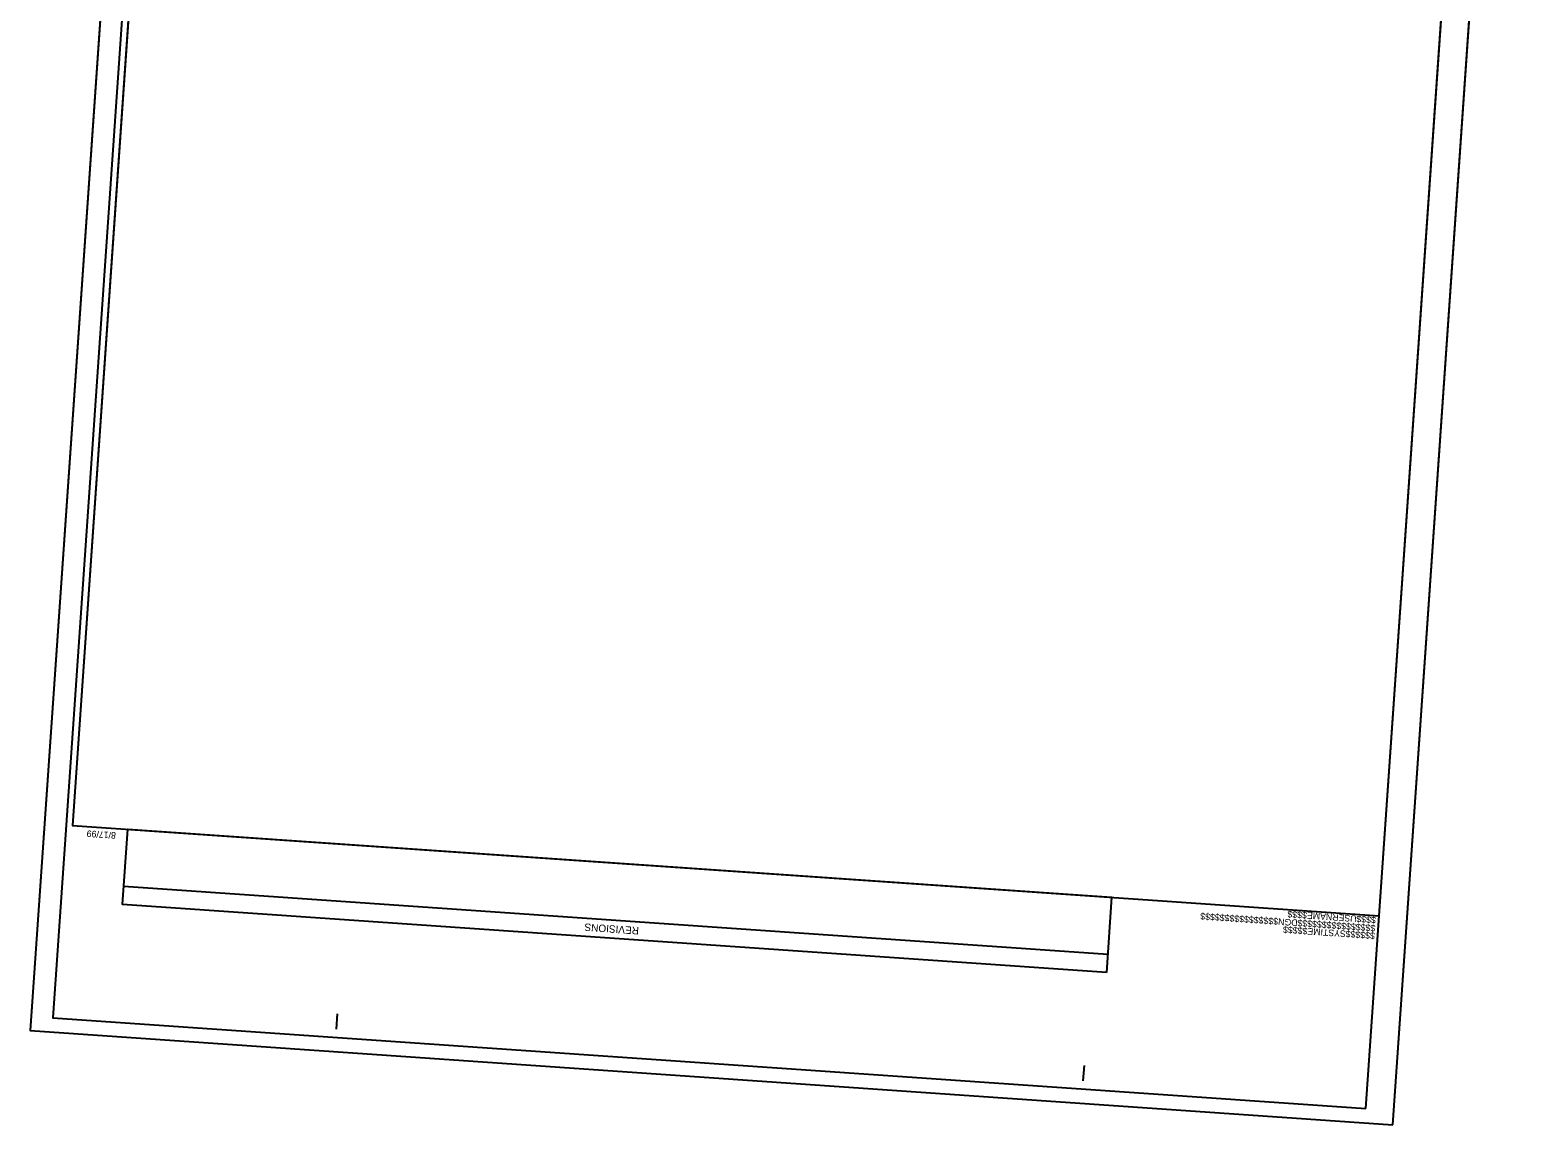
# Model space of a CAD drawing. Extents: x 2598940 to 2600149, y 728414 to 730169.
# Drawn here: x 2598940 to 2600149, y 728414 to 729291 of the extents above; entities that cross this region are included whole.
import ezdxf

# ---------------------------------------------------------------- set-up
doc = ezdxf.new("R2010")
doc.units = 0
for name, color, linetype in [('Sheet Block Revision CELL', 7, 'Continuous'), ('Sheet Clip Boundary CELL', 7, 'Continuous'), ('Sheet Cutting Line CELL', 7, 'Continuous'), ('Sheet Plan CELL', 7, 'Continuous'), ('Sheet Plot Border Inside CELL', 7, 'Continuous'), ('Sheet Plot Border Outside CELL', 7, 'Continuous')]:
    doc.layers.add(name, color=color, linetype=linetype)

msp = doc.modelspace()

# ---------------------------------------------------------------- linework, layer by layer
at = {"layer": 'Sheet Block Revision CELL'}
msp.add_line((2599804.1, 728550.2), (2599015.3, 728604.8), dxfattribs=at)
msp.add_lwpolyline([(2599803.1, 728535.7), (2599014.3, 728590.3), (2599018.5, 728650.7), (2599807.2, 728596.1)], close=True, dxfattribs=at)
at = {"layer": 'Sheet Clip Boundary CELL'}
for p, q in [((2600021.7, 728581.2), (2600125.3, 730077.7)), ((2599063.7, 729947.3), (2598974.2, 728653.7)), ((2598974.2, 728653.7), (2600021.7, 728581.2))]:
    msp.add_line(p, q, dxfattribs=at)
at = {"layer": 'Sheet Cutting Line CELL'}
for p, q in [((2599056.5, 730168.7), (2598940.3, 728489.2)), ((2600032.7, 728413.6), (2600148.9, 730093.1)), ((2598940.3, 728489.2), (2600032.7, 728413.6))]:
    msp.add_line(p, q, dxfattribs=at)
at = {"layer": 'Sheet Plan CELL'}
for p, q in [((2598974.2, 728653.7), (2598974.2, 728653.7)), ((2600021.7, 728581.2), (2600021.7, 728581.2)), ((2599186, 728490.2), (2599186.8, 728502.7)), ((2599784.5, 728448.8), (2599785.4, 728461.3))]:
    msp.add_line(p, q, dxfattribs=at)
msp.add_lwpolyline([(2599077.8, 730150.2), (2598974.2, 728653.7), (2600021.7, 728581.2), (2600125.3, 730077.7)], close=True, dxfattribs=at)
at = {"layer": 'Sheet Plot Border Inside CELL'}
msp.add_lwpolyline([(2600011, 728426.6), (2600126, 730088.6), (2599073.5, 730161.5), (2598958.5, 728499.4)], close=True, dxfattribs=at)
at = {"layer": 'Sheet Plot Border Outside CELL'}
msp.add_lwpolyline([(2600032.7, 728413.6), (2600148.9, 730093.1), (2599056.5, 730168.7), (2598940.3, 728489.2)], close=True, dxfattribs=at)

# ---------------------------------------------------------------- texts
at = {"layer": 'Sheet Block Revision CELL'}
msp.add_text('REVISIONS', height=6, rotation=176.0422, dxfattribs=at).set_placement((2599428.5, 728572.1))
at = {"layer": 'Sheet Plan CELL'}
for s, p in [('8/17/99', (2599009.2, 728648.1)), ('$$$$$$$$$$$$$$$$DGN$$$$$$$$$$$$$$$$', (2600018.8, 728573.8)), ('$$$$USERNAME$$$$', (2600019.3, 728580.3)), ('$$$$$$SYSTIME$$$$$', (2600018.5, 728567.7))]:
    msp.add_text(s, height=5.25, rotation=176.0423, dxfattribs=at).set_placement(p)

doc.saveas('drawing.dxf')
